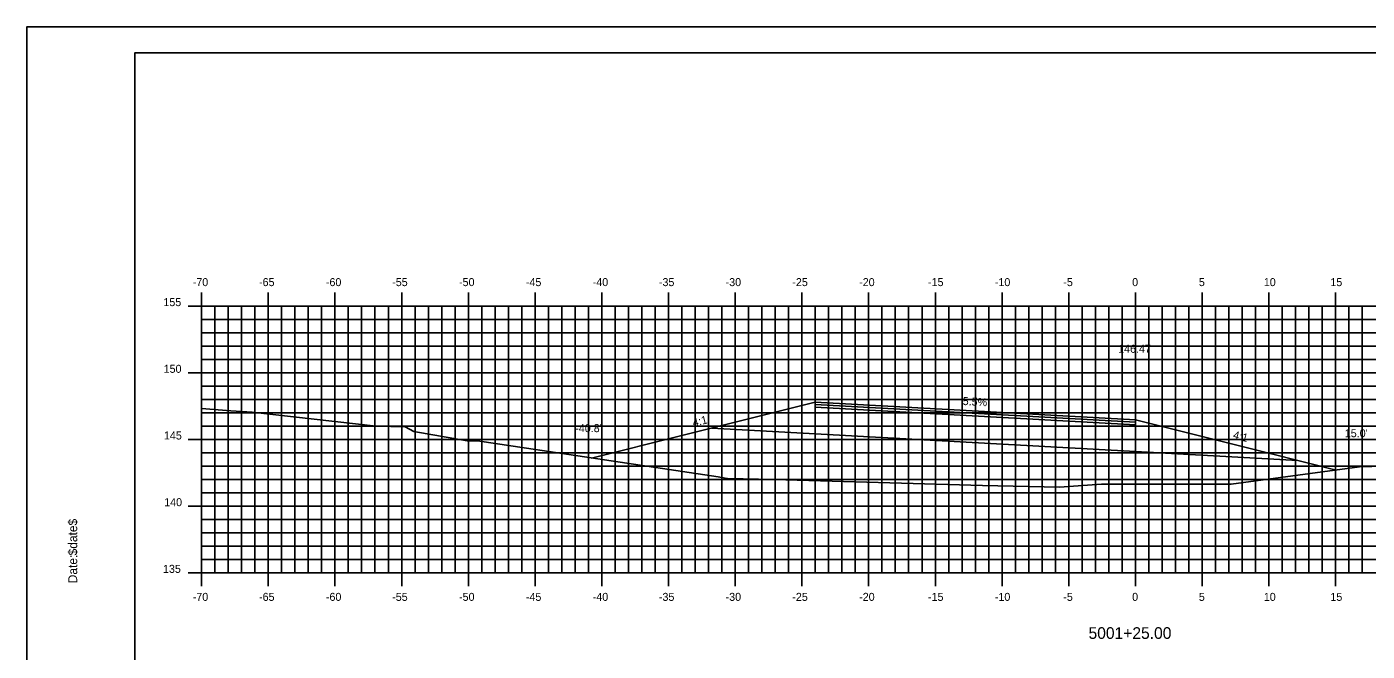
# Model space of a CAD drawing. Extents: x 850973 to 851145, y 365876 to 365986.
# Drawn here: x 850973.3 to 851073.8, y 365939 to 365985.8 of the extents above; entities that cross this region are included whole.
import ezdxf

# ---------------------------------------------------------------- set-up
doc = ezdxf.new("R2010")
doc.units = 0
for name, color, linetype in [('ANNOTATION', 7, 'Continuous'), ('BORDER', 7, 'Continuous'), ('D_Roadway_Centerline', 7, 'Continuous'), ('D_Roadway_Centerline_Text', 7, 'Continuous'), ('D_Roadway_Edge_TW', 7, 'Continuous'), ('D_Roadway_FinishedGrade', 7, 'Continuous'), ('D_Roadway_Pavement', 7, 'Continuous'), ('D_Roadway_SlopeLines', 7, 'Continuous'), ('D_Roadway_SubGrade', 7, 'Continuous'), ('D_Text_Standard', 7, 'Continuous'), ('H_V ANNOTATION', 7, 'Continuous'), ('MAJOR', 7, 'Continuous'), ('MINOR', 7, 'Continuous'), ('PLOT BOUNDARY', 7, 'Continuous'), ('S_Roadway_Centerline', 7, 'Continuous')]:
    doc.layers.add(name, color=color, linetype=linetype)

msp = doc.modelspace()

# ---------------------------------------------------------------- linework, layer by layer
at = {"layer": 'BORDER'}
msp.add_lwpolyline([(850981.39, 365878.83), (851141.39, 365878.83), (851141.39, 365983.83), (850981.39, 365983.83)], close=True, dxfattribs=at)
at = {"layer": 'D_Roadway_Centerline'}
msp.add_lwpolyline([(851015.62, 365953.44), (851022.39, 365955.13), (851032.39, 365957.63), (851056.39, 365956.3), (851066.39, 365953.8), (851071.43, 365952.54)], dxfattribs=at)
at = {"layer": 'D_Roadway_Edge_TW'}
msp.add_lwpolyline([(851032.39, 365957.63), (851056.39, 365956.3), (851056.39, 365956.13), (851032.39, 365957.46)], close=True, dxfattribs=at)
at = {"layer": 'D_Roadway_FinishedGrade'}
for p, q in [((851032.39, 365955.26), (851024.64, 365955.69)), ((851056.39, 365953.93), (851068.55, 365953.26))]:
    msp.add_line(p, q, dxfattribs=at)
at = {"layer": 'D_Roadway_Pavement'}
msp.add_lwpolyline([(851032.39, 365957.46), (851056.39, 365956.13), (851056.39, 365955.93), (851032.39, 365957.26)], close=True, dxfattribs=at)
msp.add_lwpolyline([(851056.39, 365956.13), (851056.39, 365955.93)], dxfattribs=at)
msp.add_lwpolyline([(851056.39, 365956.13), (851056.39, 365955.93)], dxfattribs=at)
at = {"layer": 'D_Roadway_SlopeLines'}
for points in [[(851032.39, 365957.63), (851022.39, 365955.13), (851015.62, 365953.44)], [(851056.39, 365956.3), (851066.39, 365953.8), (851071.43, 365952.54)]]:
    msp.add_lwpolyline(points, dxfattribs=at)
at = {"layer": 'D_Roadway_SubGrade'}
for points in [[(851032.39, 365957.26), (851056.39, 365955.93)], [(851056.39, 365953.93), (851032.39, 365955.26)]]:
    msp.add_lwpolyline(points, dxfattribs=at)
at = {"layer": 'MAJOR'}
for p, q in [((850986.39, 365965.84), (850986.39, 365964.83)), ((850991.39, 365965.84), (850991.39, 365964.83)), ((850996.39, 365965.84), (850996.39, 365964.83)), ((851001.39, 365965.84), (851001.39, 365964.83)), ((851006.39, 365965.84), (851006.39, 365964.83)), ((851011.39, 365965.84), (851011.39, 365964.83)), ((851016.39, 365965.84), (851016.39, 365964.83)), ((851021.39, 365965.84), (851021.39, 365964.83)), ((851026.39, 365965.84), (851026.39, 365964.83)), ((851031.39, 365965.84), (851031.39, 365964.83)), ((851036.39, 365965.84), (851036.39, 365964.83)), ((851041.39, 365965.84), (851041.39, 365964.83)), ((851046.39, 365965.84), (851046.39, 365964.83)), ((851051.39, 365965.84), (851051.39, 365964.83)), ((851056.39, 365965.84), (851056.39, 365964.83)), ((851061.39, 365965.84), (851061.39, 365964.83)), ((851066.39, 365965.84), (851066.39, 365964.83)), ((851071.39, 365965.84), (851071.39, 365964.83)), ((850985.38, 365964.83), (850986.39, 365964.83)), ((850986.39, 365964.83), (851126.39, 365964.83)), ((850986.39, 365944.83), (850986.39, 365964.83)), ((850986.39, 365944.83), (850986.39, 365964.83)), ((850986.39, 365964.83), (851126.39, 365964.83)), ((850991.39, 365944.83), (850991.39, 365964.83)), ((850996.39, 365944.83), (850996.39, 365964.83)), ((851001.39, 365944.83), (851001.39, 365964.83)), ((851006.39, 365944.83), (851006.39, 365964.83)), ((851011.39, 365944.83), (851011.39, 365964.83)), ((851016.39, 365944.83), (851016.39, 365964.83)), ((851021.39, 365944.83), (851021.39, 365964.83)), ((851026.39, 365944.83), (851026.39, 365964.83)), ((851031.39, 365944.83), (851031.39, 365964.83)), ((851036.39, 365944.83), (851036.39, 365964.83)), ((851041.39, 365944.83), (851041.39, 365964.83)), ((851046.39, 365944.83), (851046.39, 365964.83)), ((851051.39, 365944.83), (851051.39, 365964.83)), ((851056.39, 365944.83), (851056.39, 365964.83)), ((851061.39, 365944.83), (851061.39, 365964.83)), ((851066.39, 365944.83), (851066.39, 365964.83)), ((851071.39, 365944.83), (851071.39, 365964.83)), ((850985.38, 365959.83), (850986.39, 365959.83)), ((850986.39, 365959.83), (851126.39, 365959.83)), ((850985.38, 365954.83), (850986.39, 365954.83)), ((850986.39, 365954.83), (851126.39, 365954.83)), ((850985.38, 365949.83), (850986.39, 365949.83)), ((850986.39, 365949.83), (851126.39, 365949.83)), ((850985.38, 365944.83), (850986.39, 365944.83)), ((850986.39, 365944.83), (851126.39, 365944.83)), ((850986.39, 365944.83), (851126.39, 365944.83)), ((850986.39, 365943.83), (850986.39, 365944.83)), ((850991.39, 365943.83), (850991.39, 365944.83)), ((850996.39, 365943.83), (850996.39, 365944.83)), ((851001.39, 365943.83), (851001.39, 365944.83)), ((851006.39, 365943.83), (851006.39, 365944.83)), ((851011.39, 365943.83), (851011.39, 365944.83)), ((851016.39, 365943.83), (851016.39, 365944.83)), ((851021.39, 365943.83), (851021.39, 365944.83)), ((851026.39, 365943.83), (851026.39, 365944.83)), ((851031.39, 365943.83), (851031.39, 365944.83)), ((851036.39, 365943.83), (851036.39, 365944.83)), ((851041.39, 365943.83), (851041.39, 365944.83)), ((851046.39, 365943.83), (851046.39, 365944.83)), ((851051.39, 365943.83), (851051.39, 365944.83)), ((851056.39, 365943.83), (851056.39, 365944.83)), ((851061.39, 365943.83), (851061.39, 365944.83)), ((851066.39, 365943.83), (851066.39, 365944.83)), ((851071.39, 365943.83), (851071.39, 365944.83))]:
    msp.add_line(p, q, dxfattribs=at)
at = {"layer": 'MINOR'}
for p, q in [((850987.39, 365944.83), (850987.39, 365964.83)), ((850988.39, 365944.83), (850988.39, 365964.83)), ((850989.39, 365944.83), (850989.39, 365964.83)), ((850990.39, 365944.83), (850990.39, 365964.83)), ((850992.39, 365944.83), (850992.39, 365964.83)), ((850993.39, 365944.83), (850993.39, 365964.83)), ((850994.39, 365944.83), (850994.39, 365964.83)), ((850995.39, 365944.83), (850995.39, 365964.83)), ((850997.39, 365944.83), (850997.39, 365964.83)), ((850998.39, 365944.83), (850998.39, 365964.83)), ((850999.39, 365944.83), (850999.39, 365964.83)), ((851000.39, 365944.83), (851000.39, 365964.83)), ((851002.39, 365944.83), (851002.39, 365964.83)), ((851003.39, 365944.83), (851003.39, 365964.83)), ((851004.39, 365944.83), (851004.39, 365964.83)), ((851005.39, 365944.83), (851005.39, 365964.83)), ((851007.39, 365944.83), (851007.39, 365964.83)), ((851008.39, 365944.83), (851008.39, 365964.83)), ((851009.39, 365944.83), (851009.39, 365964.83)), ((851010.39, 365944.83), (851010.39, 365964.83)), ((851012.39, 365944.83), (851012.39, 365964.83)), ((851013.39, 365944.83), (851013.39, 365964.83)), ((851014.39, 365944.83), (851014.39, 365964.83)), ((851015.39, 365944.83), (851015.39, 365964.83)), ((851017.39, 365944.83), (851017.39, 365964.83)), ((851018.39, 365944.83), (851018.39, 365964.83)), ((851019.39, 365944.83), (851019.39, 365964.83)), ((851020.39, 365944.83), (851020.39, 365964.83)), ((851022.39, 365944.83), (851022.39, 365964.83)), ((851023.39, 365944.83), (851023.39, 365964.83)), ((851024.39, 365944.83), (851024.39, 365964.83)), ((851025.39, 365944.83), (851025.39, 365964.83)), ((851027.39, 365944.83), (851027.39, 365964.83)), ((851028.39, 365944.83), (851028.39, 365964.83)), ((851029.39, 365944.83), (851029.39, 365964.83)), ((851030.39, 365944.83), (851030.39, 365964.83)), ((851032.39, 365944.83), (851032.39, 365964.83)), ((851033.39, 365944.83), (851033.39, 365964.83)), ((851034.39, 365944.83), (851034.39, 365964.83)), ((851035.39, 365944.83), (851035.39, 365964.83)), ((851037.39, 365944.83), (851037.39, 365964.83)), ((851038.39, 365944.83), (851038.39, 365964.83)), ((851039.39, 365944.83), (851039.39, 365964.83)), ((851040.39, 365944.83), (851040.39, 365964.83)), ((851042.39, 365944.83), (851042.39, 365964.83)), ((851043.39, 365944.83), (851043.39, 365964.83)), ((851044.39, 365944.83), (851044.39, 365964.83)), ((851045.39, 365944.83), (851045.39, 365964.83)), ((851047.39, 365944.83), (851047.39, 365964.83)), ((851048.39, 365944.83), (851048.39, 365964.83)), ((851049.39, 365944.83), (851049.39, 365964.83)), ((851050.39, 365944.83), (851050.39, 365964.83)), ((851052.39, 365944.83), (851052.39, 365964.83)), ((851053.39, 365944.83), (851053.39, 365964.83)), ((851054.39, 365944.83), (851054.39, 365964.83)), ((851055.39, 365944.83), (851055.39, 365964.83)), ((851057.39, 365944.83), (851057.39, 365964.83)), ((851058.39, 365944.83), (851058.39, 365964.83)), ((851059.39, 365944.83), (851059.39, 365964.83)), ((851060.39, 365944.83), (851060.39, 365964.83)), ((851062.39, 365944.83), (851062.39, 365964.83)), ((851063.39, 365944.83), (851063.39, 365964.83)), ((851064.39, 365944.83), (851064.39, 365964.83)), ((851065.39, 365944.83), (851065.39, 365964.83)), ((851067.39, 365944.83), (851067.39, 365964.83)), ((851068.39, 365944.83), (851068.39, 365964.83)), ((851069.39, 365944.83), (851069.39, 365964.83)), ((851070.39, 365944.83), (851070.39, 365964.83)), ((851072.39, 365944.83), (851072.39, 365964.83)), ((851073.39, 365944.83), (851073.39, 365964.83)), ((850986.39, 365963.83), (851126.39, 365963.83)), ((850986.39, 365963.83), (850987.39, 365963.83)), ((850986.39, 365962.83), (851126.39, 365962.83)), ((850986.39, 365962.83), (850987.39, 365962.83)), ((850986.39, 365961.83), (851126.39, 365961.83)), ((850986.39, 365961.83), (850987.39, 365961.83)), ((850986.39, 365960.83), (851126.39, 365960.83)), ((850986.39, 365960.83), (850987.39, 365960.83)), ((850986.39, 365958.83), (851126.39, 365958.83)), ((850986.39, 365958.83), (850987.39, 365958.83)), ((850986.39, 365957.83), (851126.39, 365957.83)), ((850986.39, 365957.83), (850987.39, 365957.83)), ((850986.39, 365956.83), (851126.39, 365956.83)), ((850986.39, 365956.83), (850987.39, 365956.83)), ((850986.39, 365955.83), (851126.39, 365955.83)), ((850986.39, 365955.83), (850987.39, 365955.83)), ((850986.39, 365953.83), (851126.39, 365953.83)), ((850986.39, 365953.83), (850987.39, 365953.83)), ((850986.39, 365952.83), (851126.39, 365952.83)), ((850986.39, 365952.83), (850987.39, 365952.83)), ((850986.39, 365951.83), (851126.39, 365951.83)), ((850986.39, 365951.83), (850987.39, 365951.83)), ((850986.39, 365950.83), (851126.39, 365950.83)), ((850986.39, 365950.83), (850987.39, 365950.83)), ((850986.39, 365948.83), (851126.39, 365948.83)), ((850986.39, 365948.83), (850987.39, 365948.83)), ((850986.39, 365947.83), (851126.39, 365947.83)), ((850986.39, 365947.83), (850987.39, 365947.83)), ((850986.39, 365946.83), (851126.39, 365946.83)), ((850986.39, 365946.83), (850987.39, 365946.83)), ((850986.39, 365945.83), (851126.39, 365945.83)), ((850986.39, 365945.83), (850987.39, 365945.83))]:
    msp.add_line(p, q, dxfattribs=at)
at = {"layer": 'PLOT BOUNDARY'}
msp.add_lwpolyline([(850973.29, 365875.77), (851143.29, 365875.77), (851143.29, 365985.77), (850973.29, 365985.77)], close=True, dxfattribs=at)
at = {"layer": 'S_Roadway_Centerline'}
msp.add_lwpolyline([(850986.39, 365957.15), (850988.59, 365956.99), (850990.18, 365956.88), (850999.47, 365955.82), (851001.64, 365955.78), (851002.3, 365955.43), (851006.3, 365954.73), (851007.07, 365954.72), (851025.12, 365952.02), (851025.63, 365951.94), (851025.82, 365951.91), (851029.31, 365951.83), (851044.93, 365951.39), (851050.7, 365951.26), (851053.84, 365951.48), (851062.42, 365951.49), (851063.57, 365951.49), (851073.19, 365952.77), (851075.06, 365952.82)], dxfattribs=at)

# ---------------------------------------------------------------- texts
at = {"layer": 'ANNOTATION'}
for s, rotation, p in [('5.5%', 356.8245, (851043.43, 365957.42)), ('4:1', 14.0362, (851023.27, 365955.78)), ('4:1', 345.9638, (851063.66, 365954.91))]:
    msp.add_text(s, height=0.6, rotation=rotation, dxfattribs=at).set_placement(p)
at = {"layer": 'BORDER'}
for s, p in [('$date$', (850977.07, 365946.14)), ('Date:', (850977.07, 365944.05))]:
    msp.add_text(s, height=0.67, rotation=90, dxfattribs=at).set_placement(p)
at = {"layer": 'D_Roadway_Centerline_Text'}
msp.add_text('146.47', height=0.6, dxfattribs=at).set_placement((851055.09, 365961.33))
at = {"layer": 'D_Text_Standard'}
for s, p in [("-40.8'", (851014.4, 365955.38)), ("15.0'", (851072.08, 365955))]:
    msp.add_text(s, height=0.6, dxfattribs=at).set_placement(p)
at = {"layer": 'H_V ANNOTATION'}
for s, height, p in [('-70', 0.6, (850985.73, 365966.33)), ('-65', 0.6, (850990.7, 365966.33)), ('-60', 0.6, (850995.71, 365966.33)), ('-55', 0.6, (851000.68, 365966.33)), ('-50', 0.6, (851005.69, 365966.33)), ('-45', 0.6, (851010.7, 365966.33)), ('-40', 0.6, (851015.71, 365966.33)), ('-35', 0.6, (851020.67, 365966.33)), ('-30', 0.6, (851025.67, 365966.33)), ('-25', 0.6, (851030.67, 365966.33)), ('-20', 0.6, (851035.68, 365966.33)), ('-15', 0.6, (851040.84, 365966.33)), ('-10', 0.6, (851045.85, 365966.33)), ('-5', 0.6, (851050.98, 365966.33)), ('0', 0.6, (851056.14, 365966.33)), ('5', 0.6, (851061.14, 365966.33)), ('10', 0.6, (851066.01, 365966.33)), ('15', 0.6, (851071, 365966.33)), ('155', 0.6, (850983.53, 365964.83)), ('150', 0.6, (850983.55, 365959.83)), ('145', 0.6, (850983.57, 365954.83)), ('140', 0.6, (850983.59, 365949.83)), ('135', 0.6, (850983.5, 365944.83)), ('-70', 0.6, (850985.73, 365942.73)), ('-65', 0.6, (850990.7, 365942.73)), ('-60', 0.6, (850995.71, 365942.73)), ('-55', 0.6, (851000.68, 365942.73)), ('-50', 0.6, (851005.69, 365942.73)), ('-45', 0.6, (851010.7, 365942.73)), ('-40', 0.6, (851015.71, 365942.73)), ('-35', 0.6, (851020.67, 365942.73)), ('-30', 0.6, (851025.67, 365942.73)), ('-25', 0.6, (851030.67, 365942.73)), ('-20', 0.6, (851035.68, 365942.73)), ('-15', 0.6, (851040.84, 365942.73)), ('-10', 0.6, (851045.85, 365942.73)), ('-5', 0.6, (851050.98, 365942.73)), ('0', 0.6, (851056.14, 365942.73)), ('5', 0.6, (851061.14, 365942.73)), ('10', 0.6, (851066.01, 365942.73)), ('15', 0.6, (851071, 365942.73)), ('5001+25.00', 0.875, (851052.87, 365939.88))]:
    msp.add_text(s, height=height, dxfattribs=at).set_placement(p)
at = {"layer": 'MAJOR'}
msp.add_text('-', height=0.006, dxfattribs=at).set_placement((850986.38, 365944.83))

doc.saveas('drawing.dxf')
